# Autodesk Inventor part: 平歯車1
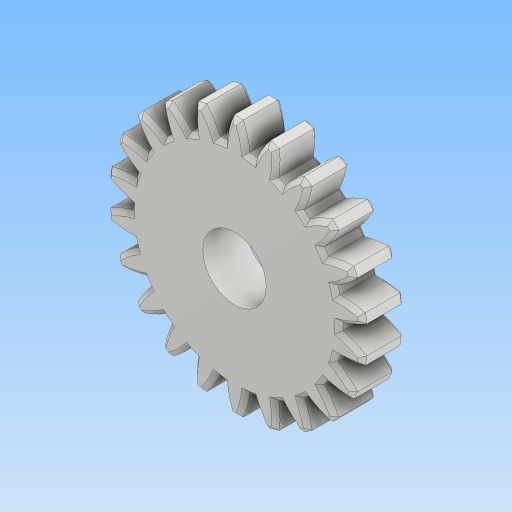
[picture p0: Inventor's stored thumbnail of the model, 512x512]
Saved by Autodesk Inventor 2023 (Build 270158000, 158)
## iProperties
CustomPartVersion: 1
Created: 2024-01
Part Number: 平歯車1
Material: Steel
Document SubType Name: Modeling
Designer: kumagai
Categories: <?xml version="1.0" encoding="UTF-16"?> <MemberInstance><Categories><FamilyTemplate><FamilyTemplateParameter ValueType="xs:double" Id="1" ObjectReferenceKey="da
Density: 1 g/cm^3
Appearance: Steel
Author: kumagai
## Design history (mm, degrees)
sketch "Sketch1"
  geometry: C1 r 12 at (0, 0); C2 r 2.95 at (0, 0); 1 further point
  constraints: 2 centre point, 2 coincident
  dimensions: "d0" = 24 diameter of C1 (= da_da); "d49" = 5.9 diameter of C2
extrude "Extrusion1" new body sketch "Sketch1" distance "d1" = 4 (= da_b); taper "d2" = 0 deg
workplane "Work Plane2"
sketch "Sketch2"
  geometry: C1 r 12 at (0, 0) reference; C2 r 11 at (0, 0)
  constraints: 1 centre point, 1 coincident
  dimensions: "d3" = 22 diameter of C2 (= da_d)
feature "ピッチ円直径" sketch "Sketch2" dims "d4" = 10, "d5" = 0
workplane "Work Plane8"
workplane "Work Plane9"
feature "平歯車" dims "da_b" = 4, "da_d" = 22, "da_aw" = 22, "da_da" = 24, "da_df" = 19.5, "da_dw" = 22, angle "da_beta" = 0 deg, "da_lefttooth" = 0, "da_righttooth" = 0
chamfer "面取り1" distance "d50" = 0.5; stored, may be unused: second distance "d51" = 2, angle "d52" = 45 deg
node "作業平面12"
chamfer "面取り2" distance "d66" = 0.4; stored, may be unused: second distance "d67" = 2, angle "d68" = 45 deg
body "Solid1"
body "Srf1"
other parameters: "d16" = 22 (= da_aw), "d17" = 0, "d34" = 1.428 (computed from da_z), "d39" = 0, "d41" = 0, "d43" = 22 (= da_aw), "d46" = 22 (= da_aw), "d47" = 0, "d48" = 0
